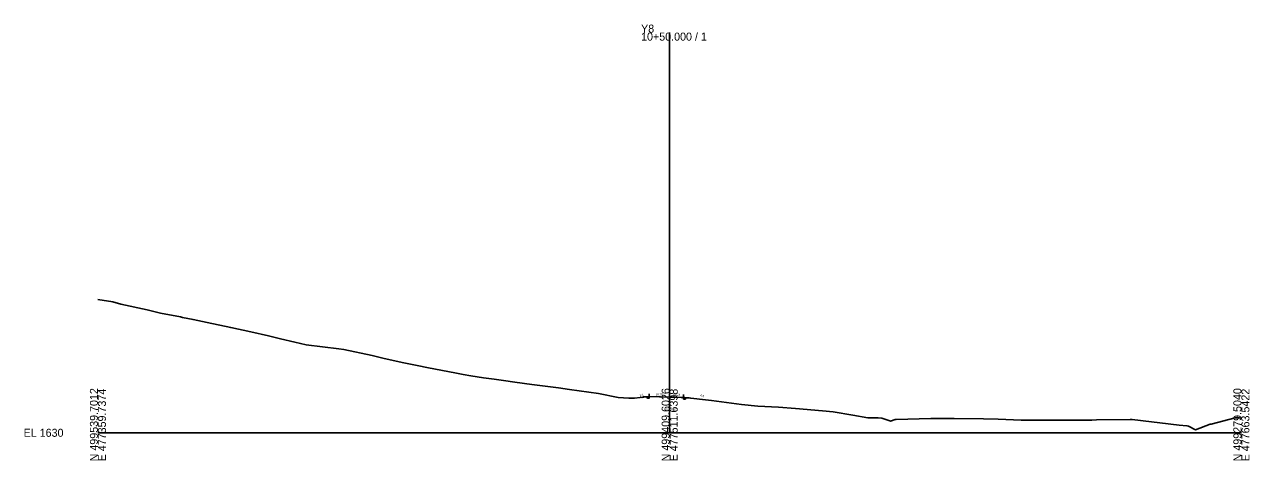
# Model space of a CAD drawing. Extents: x -26 to 403, y -10 to 2517.
# Drawn here: x -25.7 to 402.8, y 490.3 to 642.8 of the extents above; entities that cross this region are included whole.
import ezdxf

# ---------------------------------------------------------------- set-up
doc = ezdxf.new("R2010")
doc.units = 0
for name, color, linetype in [('Exist Cross Section Cell', 7, 'Continuous'), ('Exist XS Center Line Elevation Label', 7, 'Continuous'), ('Exist XS Ground Line', 7, 'Continuous'), ('Prop Road Sect_ Boring - Material (Outline)', 7, 'Continuous'), ('Prop XS Ditch Slope Text', 7, 'Continuous'), ('Prop XS Dump Level', 7, 'Continuous'), ('Prop XS Earthwork Shape', 7, 'Continuous'), ('Prop XS EOT Tick Mark', 7, 'Continuous'), ('Prop XS Finish Grade', 7, 'Continuous'), ('Prop XS Finish Grade Earthwork', 7, 'Continuous'), ('Prop XS Finish Grade Pavement', 7, 'Continuous'), ('Prop XS Hydro Typical Ditch Data', 7, 'Continuous'), ('Prop XS Pvmt Edge Slope', 7, 'Continuous'), ('Prop XS SE Text', 7, 'Continuous'), ('Prop XS Subgrade Earthwork', 7, 'Continuous'), ('Scratch_Level_6', 7, 'Continuous')]:
    doc.layers.add(name, color=color, linetype=linetype)

msp = doc.modelspace()

# ---------------------------------------------------------------- linework, layer by layer
at = {"layer": 'Exist Cross Section Cell'}
for p, q in [((200, 500), (200, 639.95)), ((0, 500), (200, 500)), ((200, 500), (400, 500))]:
    msp.add_line(p, q, dxfattribs=at)
at = {"layer": 'Exist XS Ground Line'}
msp.add_lwpolyline([(0, 546.65), (5.21, 545.81), (8.06, 544.97), (17.23, 542.95), (21.88, 541.84), (28.92, 540.5), (29.63, 540.36), (33.28, 539.56), (38.16, 538.55), (46.45, 536.77), (53.53, 535.25), (59.62, 533.9), (63.9, 532.85), (68.91, 531.65), (72.79, 530.8), (84.28, 529.36), (85.96, 529.14), (95.93, 526.97), (99.66, 526.14), (106.47, 524.58), (112.29, 523.38), (115.04, 522.88), (125.46, 520.83), (127.75, 520.41), (130.41, 519.93), (134.84, 519.26), (138.63, 518.7), (141.93, 518.33), (145.79, 517.72), (151.8, 516.89), (161.16, 515.69), (164.97, 515.09), (175.06, 513.78), (182.03, 512.38), (185.72, 512.12), (187.73, 512.14), (191.66, 512.52), (192.83, 512.66), (200, 512.47), (204.01, 512.37), (204.82, 512.35), (205.32, 512.31), (214.62, 511.25), (225.18, 509.93), (230.81, 509.36), (238.04, 508.95), (243.98, 508.44), (253.42, 507.64), (257.15, 507.32), (264.09, 506.15), (269.36, 505.25), (271.38, 505.2), (272.45, 505.27), (272.93, 505.22), (274.25, 505.1), (276.98, 504.21), (277.3, 504.08), (278.86, 504.6), (279.22, 504.7), (291.33, 504.95), (293.63, 504.98), (296.66, 505.01), (299.55, 504.95), (309.83, 504.91), (314.92, 504.76), (323, 504.37), (330.3, 504.42), (336.17, 504.38), (345.68, 504.44), (347.65, 504.46), (349.33, 504.57), (361.05, 504.63), (361.83, 504.62), (378.19, 502.69), (380.95, 502.46), (381.53, 502.33), (383.93, 501.04), (389.03, 502.99), (389.38, 503.06), (397.87, 505.27), (399.32, 505.18), (400, 505.16)], dxfattribs=at)
at = {"layer": 'Prop Road Sect_ Boring - Material (Outline)'}
for points in [[(192.83, 512.65), (192.3, 512.12), (191.81, 512.61)], [(192.83, 512.65), (192.83, 512.11), (192.3, 512.12), (191.81, 512.61)], [(192.83, 512.65), (192.3, 512.12), (191.81, 512.61)], [(192.83, 512.65), (192.83, 512.11), (192.3, 512.12), (191.81, 512.61)], [(192.83, 512.65), (192.83, 512.11), (192.3, 512.12)], [(192.83, 512.65), (192.83, 512.11), (192.3, 512.12)], [(204.82, 511.81), (205.37, 511.8), (204.82, 512.36)], [(205.37, 511.8), (205.84, 512.27), (204.82, 512.36)], [(204.82, 511.81), (205.37, 511.8), (204.82, 512.36)], [(205.37, 511.8), (205.84, 512.27), (204.82, 512.36)]]:
    msp.add_lwpolyline(points, close=True, dxfattribs=at)
at = {"layer": 'Prop XS Dump Level'}
for p, q in [((200, 512.47), (192.83, 512.65)), ((204.82, 512.36), (200, 512.47))]:
    msp.add_line(p, q, dxfattribs=at)
at = {"layer": 'Prop XS Earthwork Shape'}
for points in [[(191.88, 512.54), (191.81, 512.61), (190.82, 512.58), (190.21, 512.38), (191.66, 512.52)], [(191.88, 512.54), (192.83, 512.66), (192.83, 512.11), (192.3, 512.12)], [(204.82, 511.81), (204.82, 512.35), (205.32, 512.31), (205.82, 512.25), (205.37, 511.8)], [(205.82, 512.25), (205.84, 512.27), (206.82, 512.2), (207.25, 512.09)]]:
    msp.add_lwpolyline(points, close=True, dxfattribs=at)
at = {"layer": 'Prop XS EOT Tick Mark'}
for p, q in [((192.83, 512.65), (192.83, 513.65)), ((204.82, 512.36), (204.82, 513.36))]:
    msp.add_line(p, q, dxfattribs=at)
at = {"layer": 'Prop XS Finish Grade'}
for p, q in [((192.83, 512.65), (191.81, 512.61)), ((204.82, 512.36), (205.84, 512.27))]:
    msp.add_line(p, q, dxfattribs=at)
at = {"layer": 'Prop XS Finish Grade Earthwork'}
for p, q in [((190.82, 512.58), (190.21, 512.38)), ((191.81, 512.61), (190.82, 512.58)), ((205.84, 512.27), (206.82, 512.2)), ((206.82, 512.2), (207.25, 512.09))]:
    msp.add_line(p, q, dxfattribs=at)
at = {"layer": 'Prop XS Finish Grade Pavement'}
for p, q in [((192.83, 512.65), (200, 512.47)), ((200, 512.47), (204.82, 512.36))]:
    msp.add_line(p, q, dxfattribs=at)
at = {"layer": 'Prop XS Hydro Typical Ditch Data'}
msp.add_line((206.82, 512.2), (207.25, 512.09), dxfattribs=at)
at = {"layer": 'Prop XS Pvmt Edge Slope'}
for p, q in [((192.83, 512.65), (192.3, 512.12)), ((204.82, 512.36), (205.37, 511.8))]:
    msp.add_line(p, q, dxfattribs=at)
at = {"layer": 'Prop XS Subgrade Earthwork'}
for p, q in [((192.3, 512.12), (191.81, 512.61)), ((192.83, 512.11), (192.3, 512.12)), ((192.83, 512.66), (192.83, 512.11)), ((204.82, 511.81), (204.82, 512.35)), ((204.82, 511.81), (205.37, 511.8)), ((205.37, 511.8), (205.84, 512.27))]:
    msp.add_line(p, q, dxfattribs=at)
at = {"layer": 'Scratch_Level_6'}
msp.add_line((192.83, 512.66), (204.82, 512.35), dxfattribs=at)

# ---------------------------------------------------------------- texts
at = {"layer": 'Exist Cross Section Cell'}
for s, p in [('Y8', (190, 639.95)), ('10+50.000 / 1', (190, 637.15)), ('EL 1630', (-26, 498.6))]:
    msp.add_text(s, height=2.8, dxfattribs=at).set_placement(p)
for s, p in [('N 499539.7012', (0, 490)), ('E 477359.7374', (2.8, 490)), ('N 499409.6026', (200, 490)), ('E 477511.6398', (202.8, 490)), ('N 499279.5040', (400, 490)), ('E 477663.5422', (402.8, 490))]:
    msp.add_text(s, height=2.8, rotation=90, dxfattribs=at).set_placement(p)
at = {"layer": 'Exist XS Center Line Elevation Label'}
msp.add_text('1642.47', height=0.9, dxfattribs=at).set_placement((198.02, 507.57))
at = {"layer": 'Prop XS Ditch Slope Text'}
for s, rotation, p in [('3:1', 13.9658, (189.54, 512.7)), ('4:1', 345.9649, (210.61, 512.79))]:
    msp.add_text(s, height=0.75, rotation=rotation, dxfattribs=at).set_placement(p)
at = {"layer": 'Prop XS Dump Level'}
for p in [(190.82, 512.54), (206.82, 512.16)]:
    msp.add_text('Case1', height=0.04, dxfattribs=at).set_placement(p)
at = {"layer": 'Prop XS SE Text'}
for s, rotation, p in [('0.025', 358.5679, (195.15, 513.09)), ('0.024', 358.6252, (201.12, 512.94))]:
    msp.add_text(s, height=0.75, rotation=rotation, dxfattribs=at).set_placement(p)

doc.saveas('drawing.dxf')
